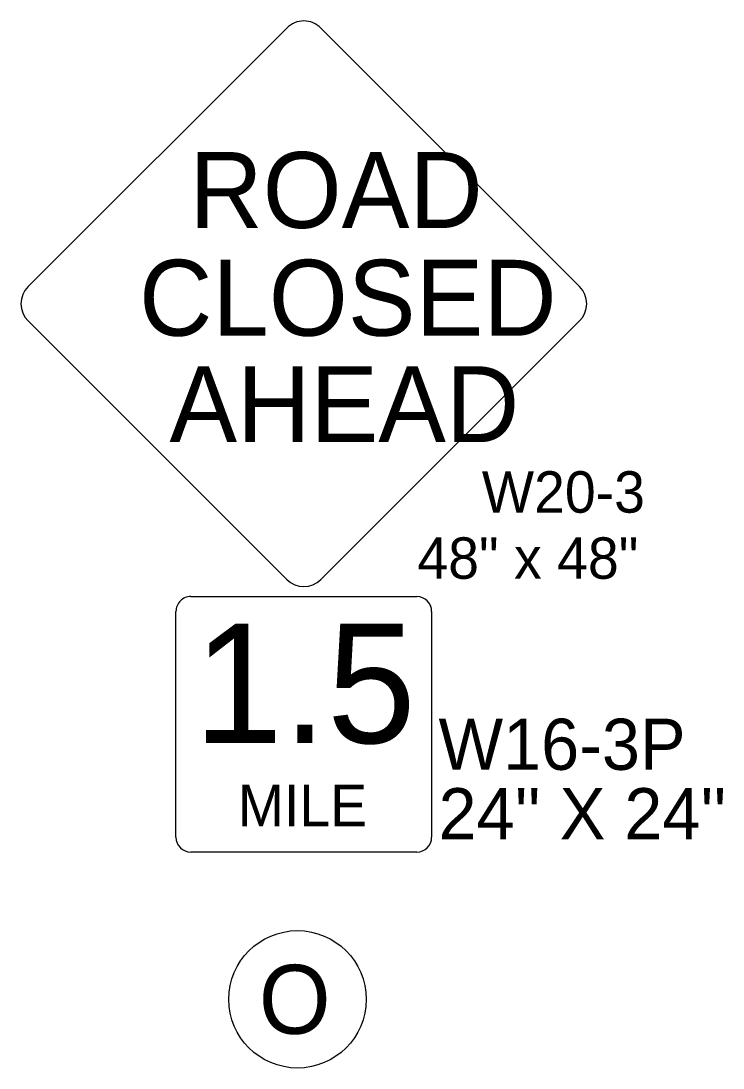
# Model space of a CAD drawing. Extents: x 2157572 to 5059327, y 715220 to 1674494.
# Drawn here: x 2168316 to 2168811, y 720618 to 721356 of the extents above; entities that cross this region are included whole.
import ezdxf

# ---------------------------------------------------------------- set-up
doc = ezdxf.new("R2010")
doc.units = 0
for name, color, linetype in [('Exist Cultural Church Label', 7, 'Continuous'), ('Exist Hydrographic Creek Single Shore Label', 7, 'Continuous'), ('Exist Road Secondary Type 20 SR Number Label', 7, 'Continuous'), ('Map Preparation County Base KeyMap CELL', 7, 'Continuous'), ('Map Preparation County Base Legend Highway Garage or Maintenance Office', 7, 'Continuous')]:
    doc.layers.add(name, color=color, linetype=linetype)

msp = doc.modelspace()

# ---------------------------------------------------------------- linework, layer by layer
at = {"layer": 'Exist Cultural Church Label'}
msp.add_circle((2168510.83, 720666.72), 48.43, dxfattribs=at)
at = {"layer": 'Exist Hydrographic Creek Single Shore Label'}
for points in [[(2168435.72, 720950.58), (2168515.27, 720950.58)], [(2168515.27, 720950.58), (2168594.82, 720950.58)], [(2168425.21, 720780.97), (2168425.21, 720940.08)], [(2168605.33, 720940.08), (2168605.33, 720780.97)], [(2168515.27, 720770.46), (2168435.72, 720770.46)], [(2168594.82, 720770.46), (2168515.27, 720770.46)]]:
    msp.add_lwpolyline(points, dxfattribs=at)
for centre, start, end in [((2168435.72, 720940.08), 89.98697, 180), ((2168594.82, 720940.08), 360, 90), ((2168435.72, 720780.97), 180, 270), ((2168594.82, 720780.97), 270, 360)]:
    msp.add_arc(centre, 10.51, start, end, dxfattribs=at)
at = {"layer": 'Exist Road Secondary Type 20 SR Number Label'}
for points in [[(2168320.97, 721168.95), (2168503.24, 721351.21)], [(2168527.31, 721351.2), (2168709.56, 721168.95)], [(2168503.24, 720962.62), (2168320.97, 721144.87)], [(2168709.56, 721144.87), (2168527.31, 720962.62)]]:
    msp.add_lwpolyline(points, dxfattribs=at)
for centre, start, end in [((2168515.27, 721339.17), 44.98697, 135), ((2168333.01, 721156.91), 135, 225), ((2168697.53, 721156.91), 315, 45), ((2168515.27, 720974.65), 225, 315)]:
    msp.add_arc(centre, 17.02, start, end, dxfattribs=at)
at = {"layer": 'Map Preparation County Base Legend Highway Garage or Maintenance Office'}
msp.add_circle((2168510.83, 720666.72), 48.43, dxfattribs=at)

# ---------------------------------------------------------------- texts
at = {"layer": 'Exist Cultural Church Label'}
msp.add_text('O', height=48.63, dxfattribs=at).set_placement((2168483.58, 720642.4))
at = {"layer": 'Exist Road Secondary Type 20 SR Number Label'}
for s, height, p in [('ROAD', 53.496, (2168434.64, 721210.31)), ('CLOSED', 53.496, (2168399.18, 721134.37)), ('AHEAD', 53.496, (2168420.58, 721059.37)), ('W20-3', 29.18, (2168640.66, 721009.66)), ('48" x 48"', 29.18, (2168595.27, 720963.09))]:
    msp.add_text(s, height=height, dxfattribs=at).set_placement(p)
at = {"layer": 'Map Preparation County Base KeyMap CELL'}
for s, height, p in [('1.5', 84.055, (2168437.87, 720847.3)), ('W16-3P', 36.024, (2168610.19, 720828.45)), ('MILE', 29.179, (2168468.79, 720788.72)), ("24'' X 24''", 36.0236, (2168610.19, 720779.52))]:
    msp.add_text(s, height=height, rotation=360, dxfattribs=at).set_placement(p)

doc.saveas('drawing.dxf')
